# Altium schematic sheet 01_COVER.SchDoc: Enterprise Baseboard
size A2; ApprovedBy: DNP; CheckedBy: DNP; Author: DNP; CompanyName: Google LLC; DrawnBy: DNP; Engineer: Bangfei/Michael/Leo; Organization: Google LLC; Address1: 1600 Amphitheatre Parkway; Address2: Mountain View, CA 94043; Address3: DNP; Address4: DNP; DocumentNumber: DNP; Revision: PVT; SheetNumber: 1; SheetTotal: 11; VersionControl_RevNumber: DNP; IsUserConfigurable: DNP
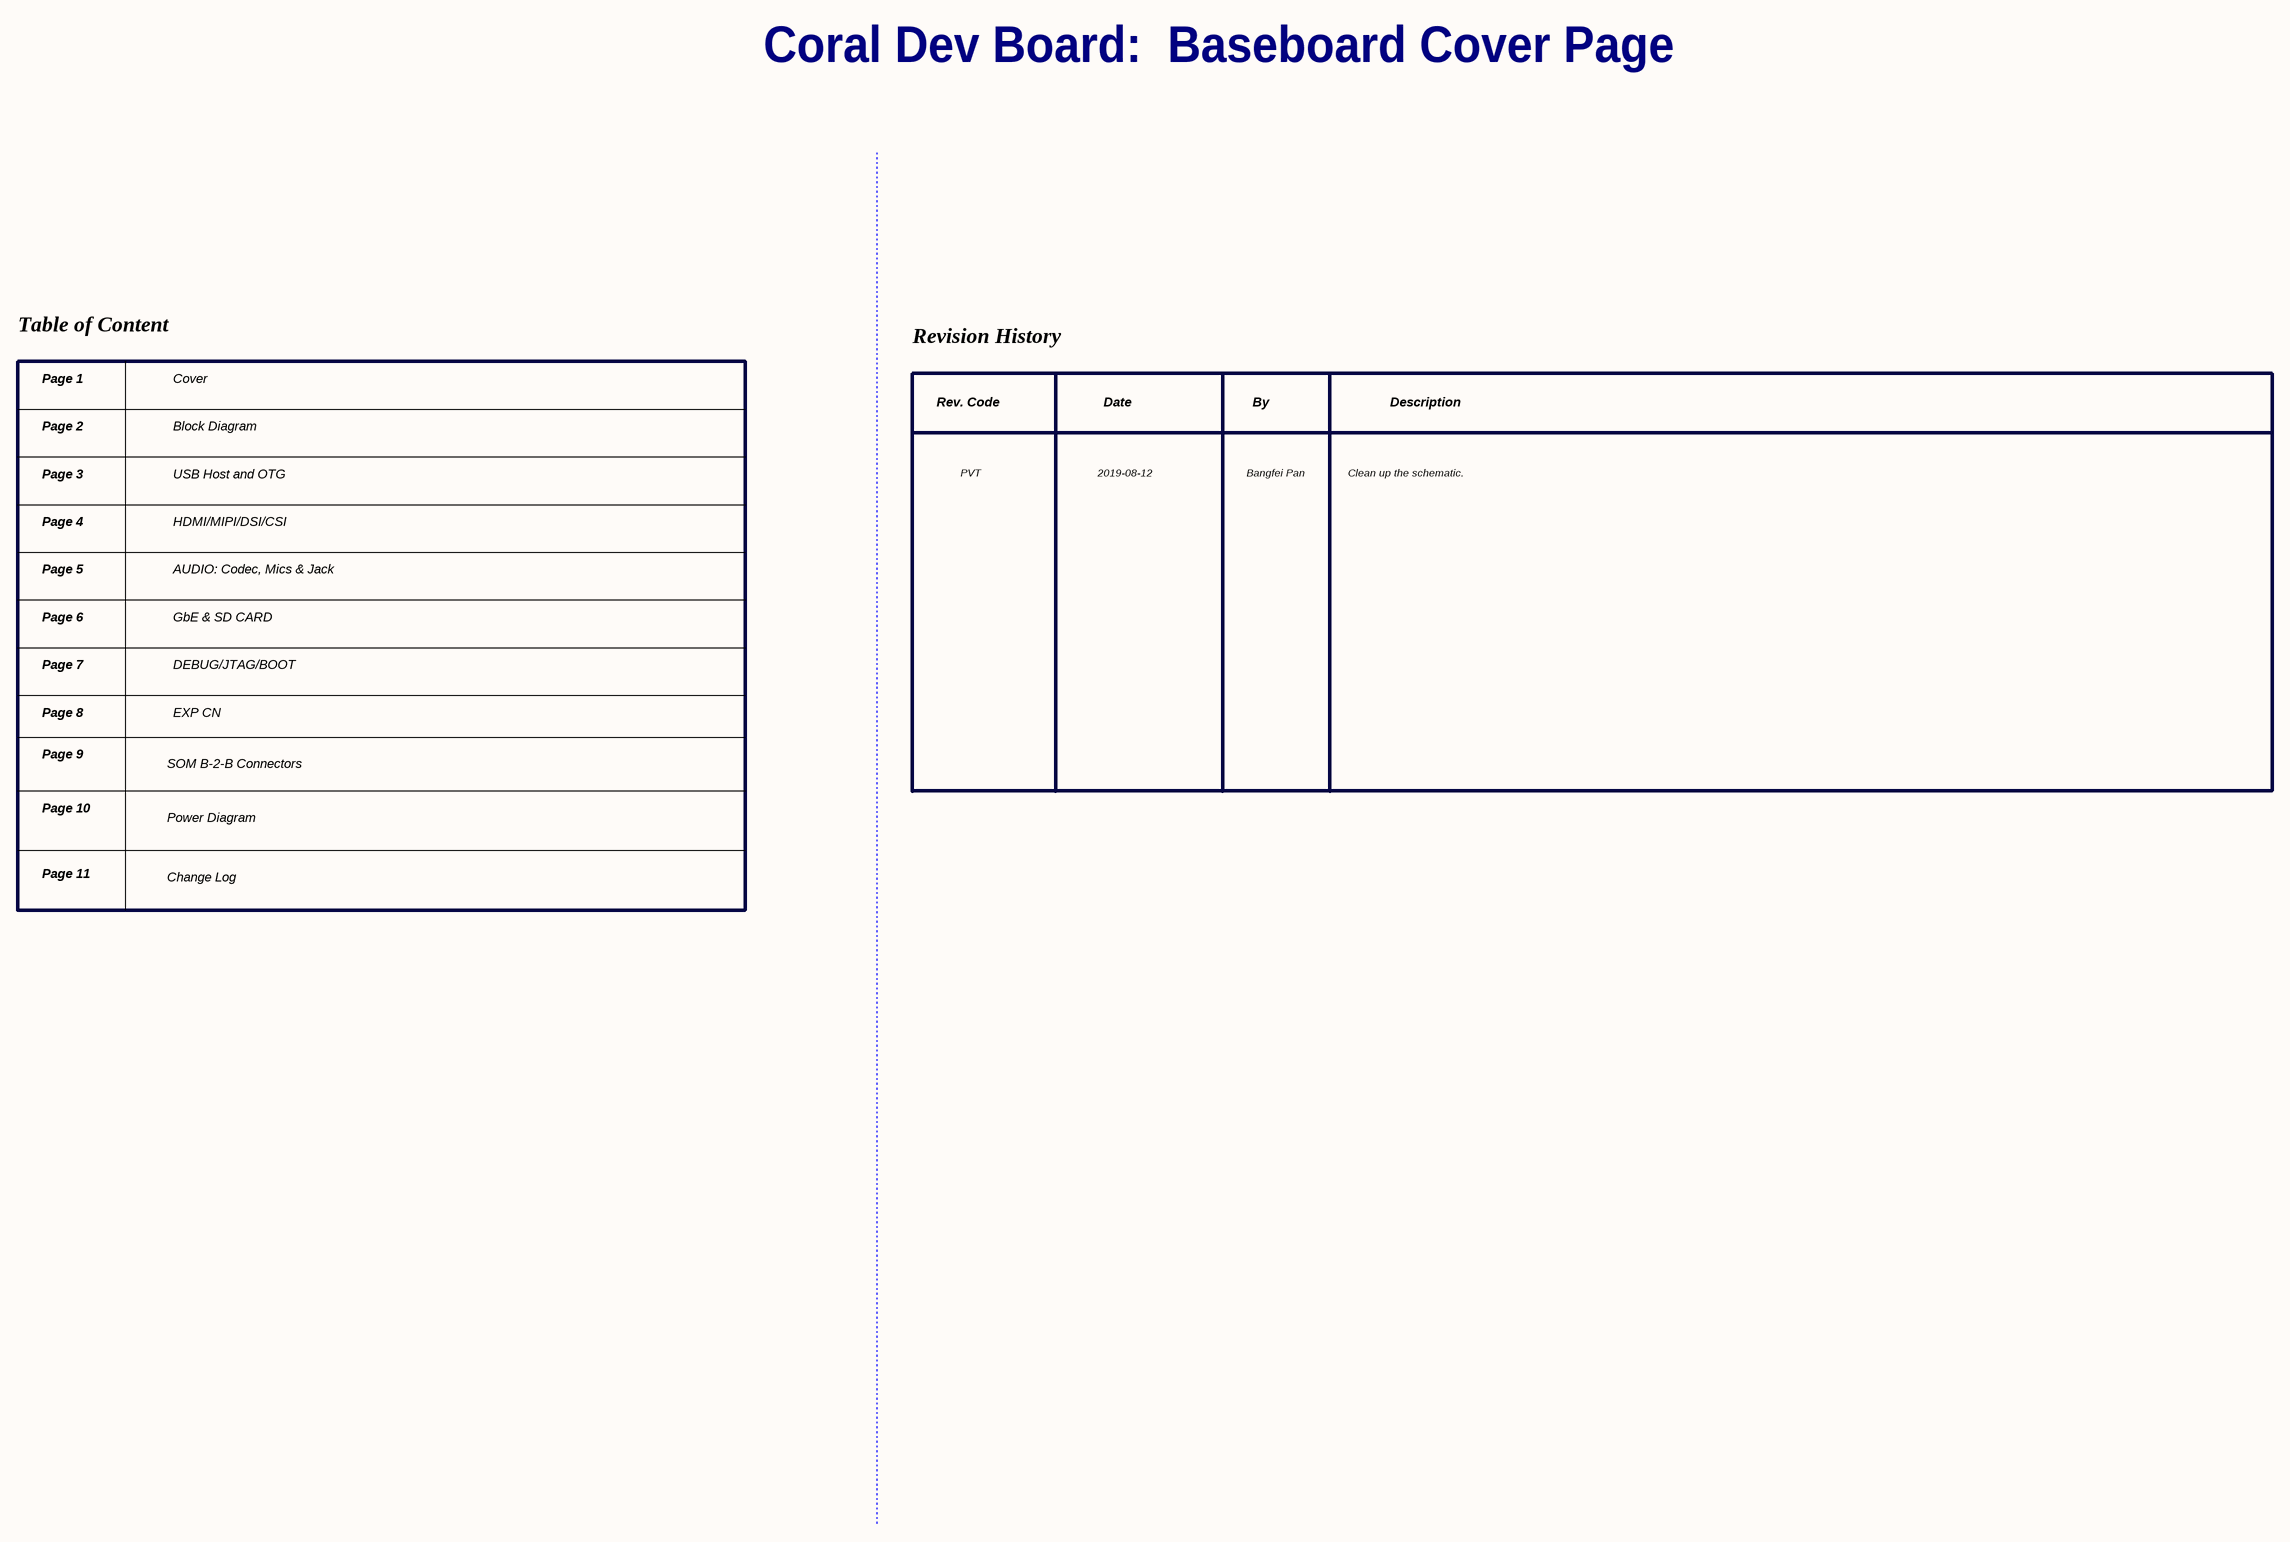
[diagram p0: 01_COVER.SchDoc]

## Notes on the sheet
- Coral Dev Board:  Baseboard Cover Page
- Table of Content
- Revision History
- Page 1
- Cover
- Rev. Code
- Date
- By
- Description
- Page 2
- Block Diagram
- Page 3
- Page 4
- USB Host and OTG
- HDMI/MIPI/DSI/CSI
- PVT
- 2019-08-12
- Bangfei Pan
- Clean up the schematic.
- Page 5
- AUDIO: Codec, Mics & Jack
- Page 6
- GbE & SD CARD
- Page 7
- DEBUG/JTAG/BOOT
- Page 8
- Page 9
- SOM B-2-B Connectors
- EXP CN
- Page 10
- Power Diagram
- Page 11
- Change Log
